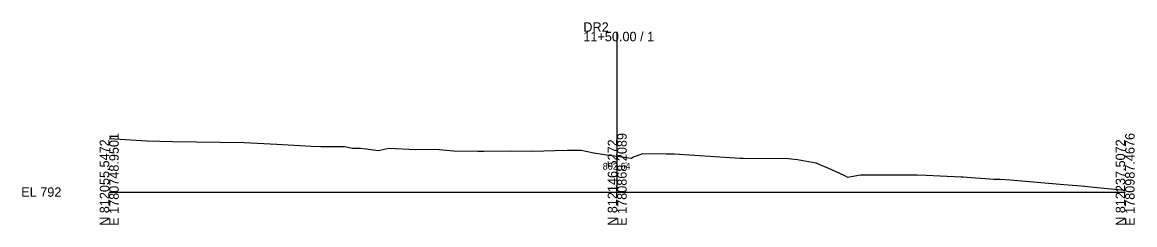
# Model space of a CAD drawing. Extents: x -26 to 303, y -10 to 2560.
# Drawn here: x -25.7 to 302.8, y 1990.3 to 2050.3 of the extents above; entities that cross this region are included whole.
import ezdxf

# ---------------------------------------------------------------- set-up
doc = ezdxf.new("R2010")
doc.units = 0
for name, color, linetype in [('Exist Cross Section Cell', 7, 'Continuous'), ('Exist XS Center Line Elevation Label', 7, 'Continuous'), ('Exist XS Ground Line', 7, 'Continuous')]:
    doc.layers.add(name, color=color, linetype=linetype)

msp = doc.modelspace()

# ---------------------------------------------------------------- linework, layer by layer
at = {"layer": 'Exist Cross Section Cell'}
for p, q in [((150, 2000), (150, 2047.44)), ((0, 2000), (150, 2000)), ((150, 2000), (300, 2000))]:
    msp.add_line(p, q, dxfattribs=at)
at = {"layer": 'Exist XS Ground Line'}
for p, q in [((0, 2015.81), (11.16, 2015.16)), ((11.16, 2015.16), (18.66, 2015.01)), ((18.66, 2015.01), (39.8, 2014.63)), ((39.8, 2014.63), (49.5, 2014.19)), ((49.5, 2014.19), (59.65, 2013.6)), ((59.65, 2013.6), (62.5, 2013.44)), ((62.5, 2013.44), (63.75, 2013.48)), ((63.75, 2013.48), (69.48, 2013.51)), ((69.48, 2013.51), (71.81, 2013.03)), ((71.81, 2013.03), (74.18, 2012.95)), ((74.18, 2012.95), (75.83, 2012.84)), ((75.83, 2012.84), (78.05, 2012.5)), ((78.05, 2012.5), (79.42, 2012.27)), ((79.42, 2012.27), (79.92, 2012.41)), ((79.92, 2012.41), (82.58, 2013.02)), ((82.58, 2013.02), (90.58, 2012.63)), ((90.58, 2012.63), (96.47, 2012.71)), ((96.47, 2012.71), (101.68, 2012.25)), ((101.68, 2012.25), (108.81, 2012.15)), ((108.81, 2012.15), (110.61, 2012.11)), ((110.61, 2012.11), (118.76, 2012.19)), ((118.76, 2012.19), (124.97, 2012.15)), ((124.97, 2012.15), (131.68, 2012.29)), ((131.68, 2012.29), (135.18, 2012.43)), ((135.18, 2012.43), (139.34, 2012.44)), ((139.34, 2012.44), (143.08, 2011.65)), ((143.08, 2011.65), (146.81, 2011.07)), ((146.81, 2011.07), (150, 2010.64)), ((150, 2010.64), (153.44, 2010.17)), ((154.66, 2010.29), (157.59, 2011.45)), ((157.59, 2011.45), (164.47, 2011.29)), ((164.47, 2011.29), (166.82, 2011.28)), ((166.82, 2011.28), (184.79, 2010.18)), ((153.44, 2010.17), (154.25, 2010.07)), ((154.25, 2010.07), (154.66, 2010.29)), ((184.79, 2010.18), (186.27, 2010)), ((186.27, 2010), (187.17, 2010.08)), ((187.17, 2010.08), (200.55, 2009.94)), ((200.55, 2009.94), (203.23, 2009.6)), ((203.23, 2009.6), (208.66, 2008.68)), ((208.66, 2008.68), (213.31, 2006.64)), ((213.31, 2006.64), (216.89, 2004.99)), ((216.89, 2004.99), (218.05, 2004.43)), ((218.05, 2004.43), (218.62, 2004.54)), ((218.62, 2004.54), (221.9, 2005.1)), ((221.9, 2005.1), (223.65, 2005.08)), ((223.65, 2005.08), (225.96, 2005.12)), ((225.96, 2005.12), (234.13, 2005.11)), ((234.13, 2005.11), (238.61, 2005.09)), ((238.61, 2005.09), (241.21, 2004.97)), ((241.21, 2004.97), (251.55, 2004.53)), ((251.55, 2004.53), (252.13, 2004.47)), ((252.13, 2004.47), (254.57, 2004.29)), ((254.57, 2004.29), (255.83, 2004.22)), ((255.83, 2004.22), (257.24, 2004.16)), ((257.24, 2004.16), (258.64, 2004.02)), ((258.64, 2004.02), (261.2, 2003.82)), ((261.2, 2003.82), (261.57, 2003.83)), ((261.57, 2003.83), (262.95, 2003.79)), ((262.95, 2003.79), (266.13, 2003.62)), ((266.13, 2003.62), (274.05, 2002.93)), ((274.05, 2002.93), (281.86, 2002.24)), ((281.86, 2002.24), (287.04, 2001.82)), ((287.04, 2001.82), (292.73, 2001.25)), ((292.73, 2001.25), (300, 2000.53))]:
    msp.add_line(p, q, dxfattribs=at)

# ---------------------------------------------------------------- texts
at = {"layer": 'Exist Cross Section Cell'}
for s, p in [('DR2', (140, 2047.44)), ('11+50.00 / 1', (140, 2044.64)), ('EL 792', (-26, 1998.6))]:
    msp.add_text(s, height=2.8, dxfattribs=at).set_placement(p)
for s, p in [('E 1780748.9501', (2.8, 1990)), ('E 1780868.2089', (152.8, 1990)), ('E 1780987.4676', (302.8, 1990)), ('N 812055.5472', (0, 1990)), ('N 812146.5272', (150, 1990)), ('N 812237.5072', (300, 1990))]:
    msp.add_text(s, height=2.8, rotation=90, dxfattribs=at).set_placement(p)
at = {"layer": 'Exist XS Center Line Elevation Label'}
msp.add_text('802.64', height=2, dxfattribs=at).set_placement((145.72, 2006.64))

doc.saveas('drawing.dxf')
